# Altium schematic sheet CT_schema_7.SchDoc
size 376 x 336 mm
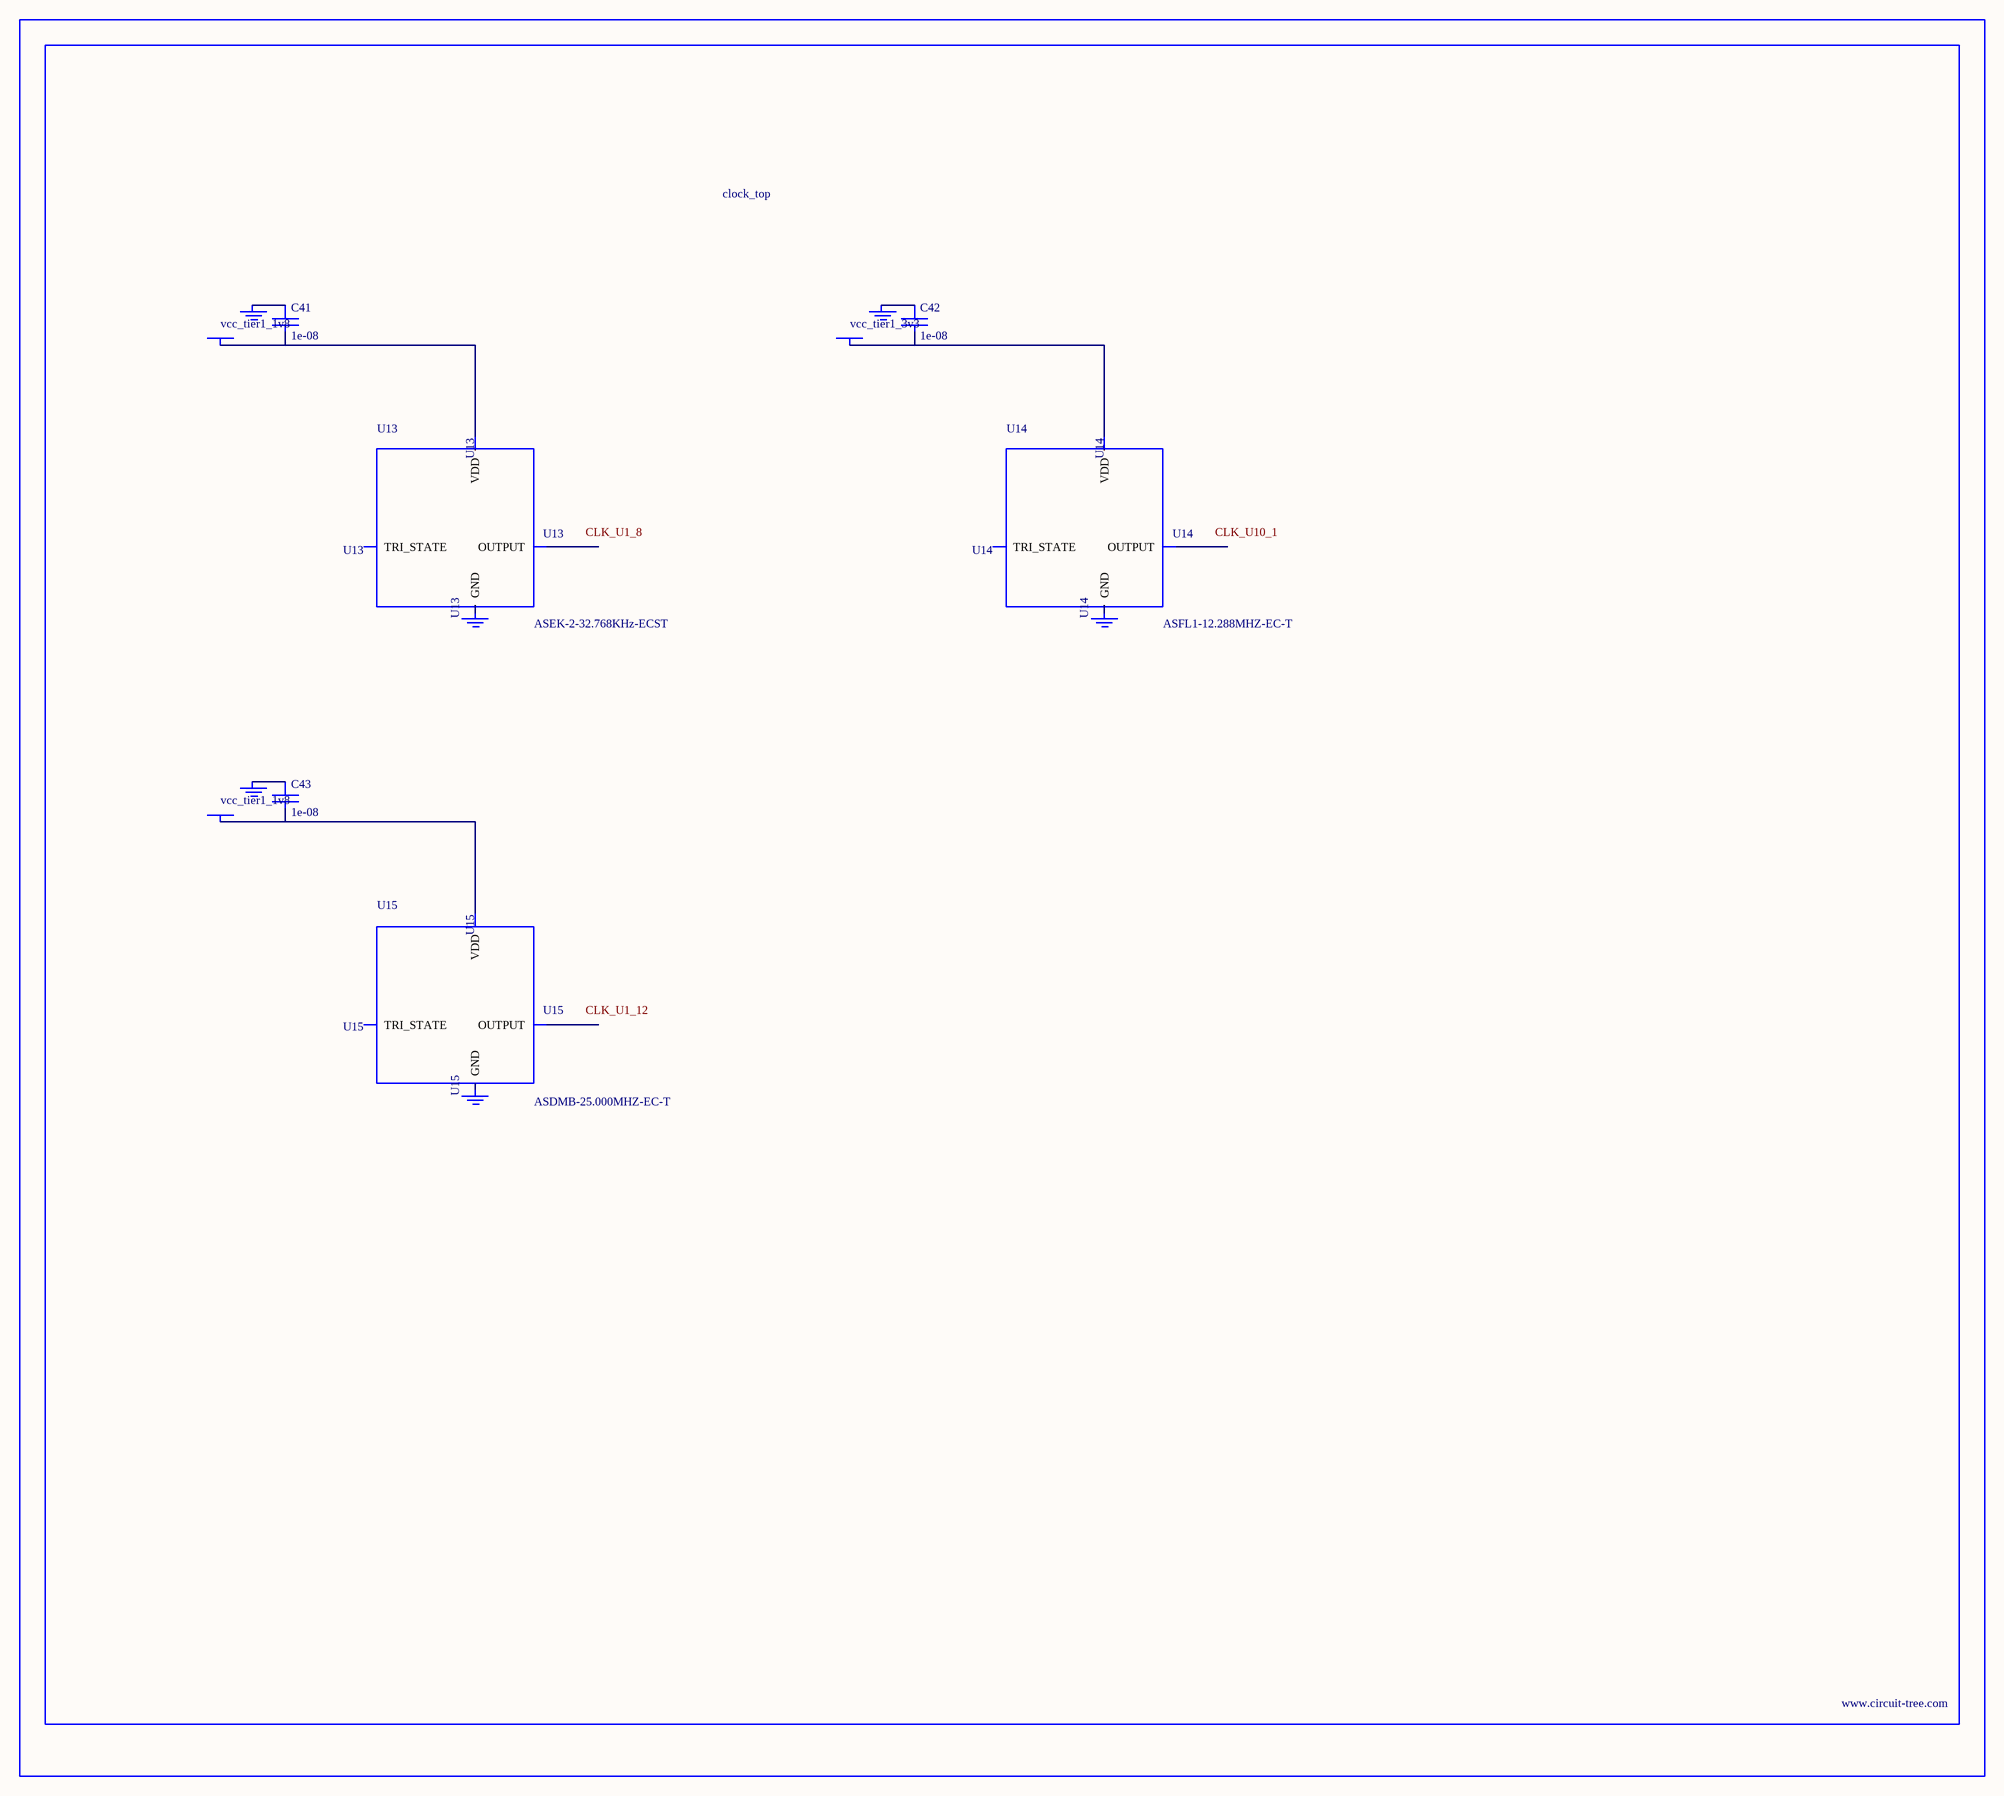
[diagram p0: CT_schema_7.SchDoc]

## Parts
BORDER6  (no value)
C41  1e-08  [C0402]
C42  1e-08  [C0402]
C43  1e-08  [C0402]
GND_INSTANCE_6_0  (no value)
GND_INSTANCE_6_1  (no value)
GND_INSTANCE_6_2  (no value)
GND_INSTANCE_6_3  (no value)
GND_INSTANCE_6_4  (no value)
GND_INSTANCE_6_5  (no value)
POWER_INSTANCE_6_0  vcc_tier1_1v8
POWER_INSTANCE_6_1  vcc_tier1_3v3
POWER_INSTANCE_6_2  vcc_tier1_1v8
U13  ASEK-2-32.768KHz-ECST  [ASEK]
U14  ASFL1-12.288MHZ-EC-T  [ASFL1]
U15  ASDMB-25.000MHZ-EC-T  [ASDMB-XX.XXXXMHZ-XX-XX-XXX]

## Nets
NetC41_1: C41.1 GND_INSTANCE_6_0.0(GND)
NetC41_2: C41.2 POWER_INSTANCE_6_0.0(PWR) U13.4(VDD)
NetC42_1: C42.1 GND_INSTANCE_6_2.0(GND)
NetC42_2: C42.2 POWER_INSTANCE_6_1.0(PWR) U14.4(VDD)
NetC43_1: C43.1 GND_INSTANCE_6_4.0(GND)
NetC43_2: C43.2 POWER_INSTANCE_6_2.0(PWR) U15.4(VDD)

Not connected (* = marked no-connect by the designer): GND_INSTANCE_6_1 0(GND); GND_INSTANCE_6_3 0(GND); GND_INSTANCE_6_5 0(GND); U13 1(TRI_STATE) 2(GND) 3(OUTPUT); U14 1(TRI_STATE) 2(GND) 3(OUTPUT); U15 1(TRI_STATE) 2(GND) 3(OUTPUT)

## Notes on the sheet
- Labels drawn without touching a wire or pin: CLK_U1_8, CLK_U1_12, CLK_U10_1

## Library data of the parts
BORDER6 = BORDER_PAGE6
C41-C43 = C0402C103K3RAC
GND_INSTANCE_6_0-GND_INSTANCE_6_5 = GND
POWER_INSTANCE_6_0-POWER_INSTANCE_6_2 = PWR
